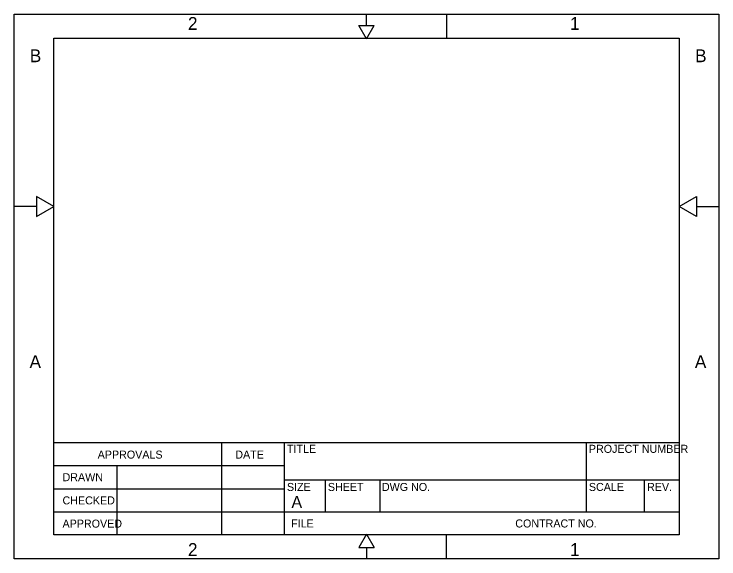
# Model space of a CAD drawing. Extents: x 0 to 0.917, y 0 to 0.708.
import ezdxf

# ---------------------------------------------------------------- set-up
doc = ezdxf.new("R2010")
doc.units = 0
for name, color, linetype in [('Border_outline', 7, 'Continuous'), ('BorderPlot', 7, 'Continuous'), ('TitleBlock', 7, 'Continuous'), ('TitleBlockText', 7, 'Continuous')]:
    doc.layers.add(name, color=color, linetype=linetype)

# ---------------------------------------------------------------- blocks, each defined once
blk = doc.blocks.new('DC-ANSI-A')
at = {"layer": 'Border_outline'}
for p, q in [((0.45833, 0.69363), (0.45833, 0.70833)), ((0.5625, 0.70833), (0.5625, 0.67708)), ((0.45833, 0.6762), (0.44827, 0.69363)), ((0.44827, 0.69363), (0.4684, 0.69363)), ((0.45833, 0.6762), (0.4684, 0.69363)), ((0.05167, 0.45833), (0.02907, 0.47138)), ((0.02907, 0.47138), (0.02907, 0.44528)), ((0.865, 0.45833), (0.8876, 0.47138)), ((0.8876, 0.47138), (0.8876, 0.44528)), ((0.02907, 0.45833), (0, 0.45833)), ((0.02907, 0.44528), (0.05167, 0.45833)), ((0.8876, 0.44528), (0.865, 0.45833)), ((0.8876, 0.45833), (0.91667, 0.45833)), ((0.45833, 0.03213), (0.44827, 0.0147)), ((0.45833, 0.03213), (0.4684, 0.0147)), ((0.5625, 0), (0.5625, 0.03125)), ((0.44827, 0.0147), (0.4684, 0.0147)), ((0.45833, 0.0147), (0.45833, 0))]:
    blk.add_line(p, q, dxfattribs=at)
blk.add_lwpolyline([(0.865, 0.03125), (0.05167, 0.03125), (0.05167, 0.67708), (0.865, 0.67708)], close=True, dxfattribs=at)
at = {"layer": 'BorderPlot'}
blk.add_lwpolyline([(0, 0.70833), (0.91667, 0.70833), (0.91667, 0), (0, 0)], close=True, dxfattribs=at)
at = {"layer": 'TitleBlock'}
for p, q in [((0.05167, 0.15125), (0.865, 0.15125)), ((0.27038, 0.03125), (0.27038, 0.15125)), ((0.3517, 0.03125), (0.3517, 0.15125)), ((0.74431, 0.06125), (0.74431, 0.15125)), ((0.05167, 0.12125), (0.3517, 0.12125)), ((0.13396, 0.03125), (0.13396, 0.12125)), ((0.3517, 0.10292), (0.865, 0.10292)), ((0.40489, 0.06125), (0.40489, 0.10292)), ((0.47606, 0.06125), (0.47606, 0.10292)), ((0.81988, 0.06125), (0.81988, 0.10292)), ((0.05167, 0.09125), (0.3517, 0.09125)), ((0.05167, 0.06125), (0.865, 0.06125)), ((0.865, 0.03125), (0.865, 0.03125))]:
    blk.add_line(p, q, dxfattribs=at)
at = {"layer": 'Border_outline'}
for s, p in [('2', (0.22613, 0.68784)), ('2', (0.22613, 0.68784)), ('1', (0.72308, 0.68784)), ('B', (0.02043, 0.64582)), ('B', (0.88573, 0.64582)), ('A', (0.02013, 0.24816)), ('A', (0.88543, 0.24816)), ('2', (0.22613, 0.00383)), ('1', (0.72308, 0.00383))]:
    blk.add_text(s, height=0.01667, dxfattribs=at).set_placement(p)
at = {"layer": 'TitleBlock'}
blk.add_text('A', height=0.01562, dxfattribs=at).set_placement((0.3607, 0.06619))
at = {"layer": 'TitleBlockText'}
for s, height, p in [('TITLE', 0.010417, (0.35488, 0.13789)), ('PROJECT NUMBER', 0.0104167, (0.74755, 0.13789)), ('APPROVALS', 0.010417, (0.1087, 0.13042)), ('DATE', 0.010417, (0.28772, 0.13042)), ('DRAWN', 0.010417, (0.06299, 0.10104)), ('SIZE', 0.010417, (0.35488, 0.08834)), ('SHEET', 0.010417, (0.4081, 0.08834)), ('DWG NO.', 0.010417, (0.47839, 0.08834)), ('SCALE', 0.010417, (0.74755, 0.08834)), ('REV.', 0.010417, (0.82321, 0.08834)), ('CHECKED', 0.010417, (0.06299, 0.07086)), ('APPROVED', 0.010417, (0.06299, 0.04067)), ('FILE', 0.010417, (0.36032, 0.04088)), ('CONTRACT NO.', 0.0104167, (0.65183, 0.04088))]:
    blk.add_text(s, height=height, dxfattribs=at).set_placement(p)

msp = doc.modelspace()

# ---------------------------------------------------------------- block references
msp.add_blockref('DC-ANSI-A', (0, 0))

doc.saveas('drawing.dxf')
